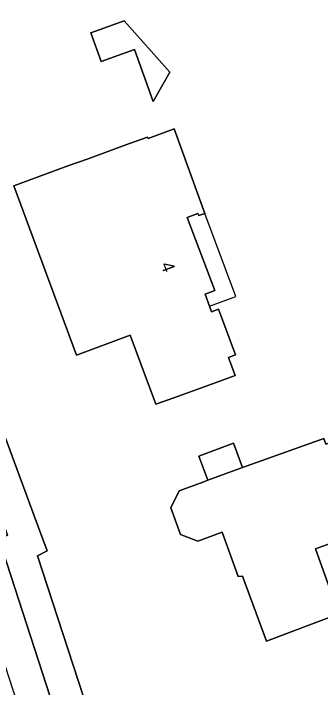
# Model space of a CAD drawing. Extents: x 159499 to 160349, y 382524 to 383273.
# Drawn here: x 159751.6 to 159775.7, y 382853 to 382906.1 of the extents above; entities that cross this region are included whole.
import ezdxf

# ---------------------------------------------------------------- set-up
doc = ezdxf.new("R2010")
doc.units = 0
for name, color, linetype in [('IMGEO_Erf', 7, 'Continuous'), ('IMGEO_Groenvoorziening', 7, 'Continuous'), ('IMGEO_Pand', 7, 'Continuous'), ('IMGEO_Pand_nummerreeks', 7, 'Continuous'), ('IMGEO_Pand_overbouw', 7, 'Continuous')]:
    doc.layers.add(name, color=color, linetype=linetype)

msp = doc.modelspace()

# ---------------------------------------------------------------- linework, layer by layer
at = {"layer": 'IMGEO_Erf'}
msp.add_lwpolyline([(159797.571, 382912.547), (159772.924, 382944.336), (159765.561, 382953.83), (159760.969, 382951.204), (159750.017, 382945.267), (159739.773, 382940.307), (159729.278, 382935.832), (159728.417, 382938.099), (159719.333, 382934.542), (159720.458, 382931.079), (159730.546, 382899.75), (159741.202, 382899.547), (159744.626, 382889.831), (159753.21, 382866.555), (159754.229, 382863.79), (159753.482, 382863.418), (159757.881, 382849.879), (159758.599, 382850.174), (159770.661, 382815.939), (159788.308, 382822.433), (159800.223, 382826.817), (159778.58, 382886.258)], dxfattribs=at)
for points in [[(159762.581, 382899.19), (159761.111, 382903.271), (159758.477, 382902.322), (159757.664, 382904.58), (159760.298, 382905.529), (159763.893, 382901.5)], [(159766.629, 382890.365), (159766.17, 382890.193), (159766.103, 382890.371), (159765.26, 382890.056), (159767.416, 382884.29), (159766.669, 382883.998), (159767.007, 382883.078), (159767.172, 382882.628), (159767.726, 382882.831), (159769.048, 382879.231), (159768.494, 382879.029), (159769.017, 382877.594), (159767.542, 382877.055), (159764.194, 382875.844), (159762.78, 382875.34), (159760.774, 382880.779), (159756.533, 382879.215), (159751.617, 382892.543), (159755.938, 382894.13), (159757.376, 382894.639), (159760.708, 382895.873), (159762.138, 382896.381), (159762.182, 382896.264), (159764.216, 382897.024)], [(159780.023, 382873.596), (159782.547, 382866.591), (159775.336, 382863.944), (159777.169, 382858.827), (159771.481, 382856.693), (159769.61, 382861.8), (159769.254, 382861.771), (159768.009, 382865.276), (159766.087, 382864.568), (159764.729, 382865.078), (159763.977, 382867.195), (159764.632, 382868.52), (159766.556, 382869.235), (159766.874, 382869.353), (159766.164, 382871.264), (159768.897, 382872.28), (159769.609, 382870.363), (159775.995, 382872.653), (159776.167, 382872.186)]]:
    msp.add_lwpolyline(points, close=True, dxfattribs=at)
at = {"layer": 'IMGEO_Groenvoorziening'}
msp.add_lwpolyline([(159802.405, 382822.292), (159800.752, 382827.014), (159800.223, 382826.817), (159788.308, 382822.433), (159788.827, 382821.022), (159771.392, 382812.521), (159757.881, 382849.879), (159753.482, 382863.418), (159754.229, 382863.79), (159753.21, 382866.555), (159744.626, 382889.831), (159741.202, 382899.547), (159730.546, 382899.75), (159731.353, 382897.234), (159739.421, 382897.08), (159751.108, 382865.029), (159750.438, 382864.695), (159756.337, 382846.542), (159757.115, 382846.862), (159769.976, 382810.359)], close=True, dxfattribs=at)
msp.add_lwpolyline([(159803.042, 382820.472), (159802.405, 382822.292), (159769.976, 382810.359), (159757.115, 382846.862), (159756.337, 382846.542), (159750.438, 382864.695), (159751.108, 382865.029), (159739.421, 382897.08), (159731.353, 382897.234), (159732.164, 382894.706), (159737.708, 382895.57), (159759.661, 382827.691), (159765.488, 382806.454), (159767.125, 382805.829), (159767.559, 382806.835), (159774.261, 382804.239), (159773.875, 382803.253), (159775.647, 382802.577)], dxfattribs=at)
at = {"layer": 'IMGEO_Pand'}
for points in [[(159758.477, 382902.322), (159761.111, 382903.271), (159762.581, 382899.19), (159763.893, 382901.5), (159760.298, 382905.529), (159757.664, 382904.58)], [(159765.26, 382890.056), (159766.103, 382890.371), (159766.17, 382890.193), (159766.629, 382890.365), (159764.216, 382897.024), (159762.182, 382896.264), (159762.138, 382896.381), (159760.708, 382895.873), (159757.376, 382894.639), (159755.938, 382894.13), (159751.617, 382892.543), (159756.533, 382879.215), (159760.774, 382880.779), (159762.78, 382875.34), (159764.194, 382875.844), (159767.542, 382877.055), (159769.017, 382877.594), (159768.494, 382879.029), (159769.048, 382879.231), (159767.726, 382882.831), (159767.172, 382882.628), (159767.007, 382883.078), (159766.669, 382883.998), (159767.416, 382884.29)], [(159780.023, 382873.596), (159776.167, 382872.186), (159775.995, 382872.653), (159769.609, 382870.363), (159766.874, 382869.353), (159766.556, 382869.235), (159764.632, 382868.52), (159763.977, 382867.195), (159764.729, 382865.078), (159766.087, 382864.568), (159768.009, 382865.276), (159769.254, 382861.771), (159769.61, 382861.8), (159771.481, 382856.693), (159777.169, 382858.827), (159775.336, 382863.944), (159782.547, 382866.591)], [(159766.874, 382869.353), (159769.609, 382870.363), (159768.897, 382872.28), (159766.164, 382871.264)]]:
    msp.add_lwpolyline(points, close=True, dxfattribs=at)
at = {"layer": 'IMGEO_Pand_overbouw'}
msp.add_lwpolyline([(159766.629, 382890.365), (159766.17, 382890.193), (159766.103, 382890.371), (159765.26, 382890.056), (159767.416, 382884.29), (159766.669, 382883.998), (159767.007, 382883.078), (159769.069, 382883.838)], close=True, dxfattribs=at)

# ---------------------------------------------------------------- texts
at = {"layer": 'IMGEO_Pand_nummerreeks'}
msp.add_text('4', height=1, rotation=290.4945, dxfattribs=at).set_placement((159763.148, 382886.342))

doc.saveas('drawing.dxf')
